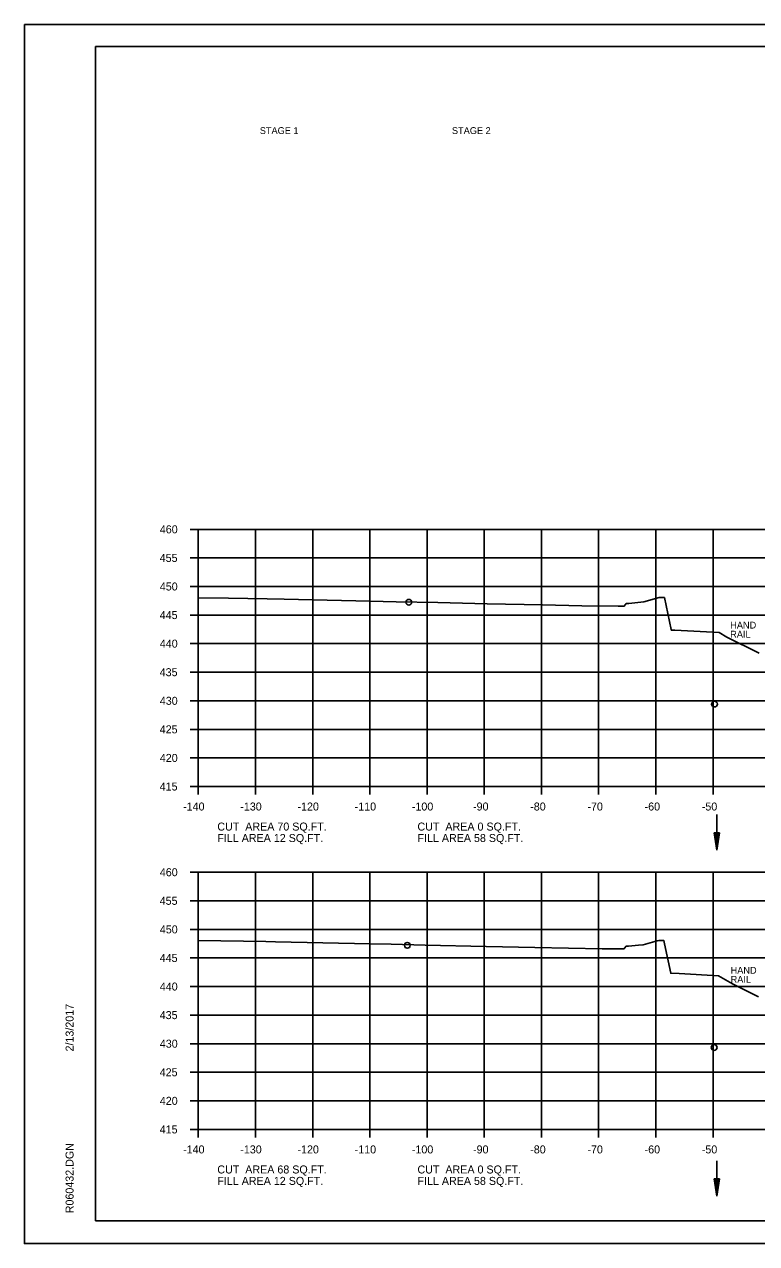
# Model space of a CAD drawing. Extents: x 1538688 to 1540766, y 656250 to 671912.
# Drawn here: x 1538687.8 to 1538815.8, y 663804.7 to 664018.1 of the extents above; entities that cross this region are included whole.
import ezdxf

# ---------------------------------------------------------------- set-up
doc = ezdxf.new("R2010")
doc.units = 0
for name, color, linetype in [('15', 7, 'Continuous'), ('18', 7, 'Continuous'), ('22', 7, 'Continuous'), ('26', 7, 'Continuous'), ('39', 7, 'Continuous'), ('41', 7, 'Continuous'), ('Borings', 7, 'Continuous'), ('Default', 7, 'Continuous'), ('Horizontal Alignment', 7, 'Continuous'), ('RipRap', 7, 'Continuous')]:
    doc.layers.add(name, color=color, linetype=linetype)

msp = doc.modelspace()

# ---------------------------------------------------------------- linework, layer by layer
at = {"layer": '15'}
for p, q in [((1538808.41, 663876.6), (1538808.86, 663873.6)), ((1538808.41, 663876.6), (1538809.31, 663876.6)), ((1538808.48, 663876.6), (1538808.86, 663874.1)), ((1538808.56, 663876.6), (1538808.86, 663874.62)), ((1538808.63, 663876.6), (1538808.86, 663875.12)), ((1538808.71, 663876.6), (1538808.86, 663875.63)), ((1538808.79, 663876.6), (1538808.86, 663876.13)), ((1538809.31, 663876.6), (1538808.86, 663873.6)), ((1538809, 663876.6), (1538808.86, 663875.63)), ((1538809.16, 663876.6), (1538808.86, 663874.62)), ((1538809.23, 663876.6), (1538808.86, 663874.1)), ((1538809.08, 663876.6), (1538808.86, 663875.12)), ((1538808.93, 663876.6), (1538808.86, 663876.13)), ((1538808.41, 663816.04), (1538808.86, 663813.04)), ((1538808.41, 663816.04), (1538809.31, 663816.04)), ((1538808.48, 663816.04), (1538808.86, 663813.54)), ((1538808.56, 663816.04), (1538808.86, 663814.06)), ((1538808.63, 663816.04), (1538808.86, 663814.56)), ((1538808.71, 663816.04), (1538808.86, 663815.06)), ((1538808.79, 663816.04), (1538808.86, 663815.57)), ((1538809.31, 663816.04), (1538808.86, 663813.04)), ((1538809, 663816.04), (1538808.86, 663815.06)), ((1538809.16, 663816.04), (1538808.86, 663814.06)), ((1538809.23, 663816.04), (1538808.86, 663813.54)), ((1538809.08, 663816.04), (1538808.86, 663814.56)), ((1538808.93, 663816.04), (1538808.86, 663815.57))]:
    msp.add_line(p, q, dxfattribs=at)
at = {"layer": '18'}
for points in [[(1538718.18, 663917.75), (1538723.43, 663917.68), (1538730.23, 663917.55), (1538733.18, 663917.48), (1538748.22, 663917.13), (1538752.76, 663917.04), (1538760.05, 663916.88), (1538768.68, 663916.68), (1538778.39, 663916.48), (1538785.26, 663916.34), (1538791.57, 663916.27), (1538792.66, 663916.29), (1538792.81, 663916.48), (1538793.01, 663916.74), (1538793.2, 663916.74), (1538793.46, 663916.74), (1538796.06, 663917), (1538796.08, 663917.01), (1538796.09, 663917.01), (1538798.77, 663917.77), (1538798.79, 663917.77), (1538799.67, 663917.77), (1538800.87, 663912.16), (1538800.88, 663912.09), (1538801.53, 663912.06), (1538809.25, 663911.65), (1538810.6, 663910.86), (1538816.24, 663908.05)], [(1538718.18, 663857.78), (1538726.08, 663857.67), (1538729.97, 663857.6), (1538731.67, 663857.56), (1538748.26, 663857.17), (1538751.92, 663857.1), (1538757.84, 663856.97), (1538768.49, 663856.73), (1538777.04, 663856.55), (1538788.82, 663856.31), (1538791.25, 663856.28), (1538792.62, 663856.3), (1538792.71, 663856.43), (1538792.97, 663856.75), (1538793.09, 663856.75), (1538793.42, 663856.75), (1538795.15, 663856.93), (1538795.99, 663857.01), (1538798.41, 663857.7), (1538798.68, 663857.76), (1538799.5, 663857.77), (1538799.58, 663857.77), (1538799.69, 663857.21), (1538800.79, 663852.04), (1538802.24, 663851.97), (1538809.13, 663851.61), (1538811.59, 663850.16), (1538816.15, 663847.9)]]:
    msp.add_lwpolyline(points, dxfattribs=at)
at = {"layer": '22'}
for p, q in [((1538718.18, 663929.71), (1538998.18, 663929.71)), ((1538718.18, 663884.71), (1538718.18, 663929.71)), ((1538728.18, 663884.71), (1538728.18, 663929.71)), ((1538738.18, 663884.71), (1538738.18, 663929.71)), ((1538748.18, 663884.71), (1538748.18, 663929.71)), ((1538758.18, 663884.71), (1538758.18, 663929.71)), ((1538768.18, 663884.71), (1538768.18, 663929.71)), ((1538778.18, 663884.71), (1538778.18, 663929.71)), ((1538788.18, 663884.71), (1538788.18, 663929.71)), ((1538798.18, 663884.71), (1538798.18, 663929.71)), ((1538808.18, 663884.71), (1538808.18, 663929.71)), ((1538718.18, 663924.71), (1538998.18, 663924.71)), ((1538718.18, 663919.71), (1538998.18, 663919.71)), ((1538718.18, 663914.71), (1538998.18, 663914.71)), ((1538718.18, 663909.71), (1538998.18, 663909.71)), ((1538718.18, 663904.71), (1538998.18, 663904.71)), ((1538718.18, 663899.71), (1538998.18, 663899.71)), ((1538718.18, 663894.71), (1538998.18, 663894.71)), ((1538718.18, 663889.71), (1538998.18, 663889.71)), ((1538718.18, 663884.71), (1538998.18, 663884.71)), ((1538718.18, 663869.71), (1538998.18, 663869.71)), ((1538718.18, 663824.71), (1538718.18, 663869.71)), ((1538728.18, 663824.71), (1538728.18, 663869.71)), ((1538738.18, 663824.71), (1538738.18, 663869.71)), ((1538748.18, 663824.71), (1538748.18, 663869.71)), ((1538758.18, 663824.71), (1538758.18, 663869.71)), ((1538768.18, 663824.71), (1538768.18, 663869.71)), ((1538778.18, 663824.71), (1538778.18, 663869.71)), ((1538788.18, 663824.71), (1538788.18, 663869.71)), ((1538798.18, 663824.71), (1538798.18, 663869.71)), ((1538808.18, 663824.71), (1538808.18, 663869.71)), ((1538718.18, 663864.71), (1538998.18, 663864.71)), ((1538718.18, 663859.71), (1538998.18, 663859.71)), ((1538718.18, 663854.71), (1538998.18, 663854.71)), ((1538718.18, 663849.71), (1538998.18, 663849.71)), ((1538718.18, 663844.71), (1538998.18, 663844.71)), ((1538718.18, 663839.71), (1538998.18, 663839.71)), ((1538718.18, 663834.71), (1538998.18, 663834.71)), ((1538718.18, 663829.71), (1538998.18, 663829.71)), ((1538718.18, 663824.71), (1538998.18, 663824.71))]:
    msp.add_line(p, q, dxfattribs=at)
at = {"layer": '26'}
for p, q in [((1538687.78, 664018.06), (1539021.11, 664018.06)), ((1538687.78, 663804.73), (1539021.11, 663804.73))]:
    msp.add_line(p, q, dxfattribs=at)
msp.add_lwpolyline([(1538687.77, 664018.06), (1539021.11, 664018.06), (1539021.11, 663804.73), (1538687.77, 663804.73)], close=True, dxfattribs=at)
for centre in [(1538754.99, 663916.95), (1538808.44, 663899.13), (1538754.73, 663856.92), (1538808.38, 663839.04)]:
    msp.add_circle(centre, 0.5, dxfattribs=at)
at = {"layer": '39'}
for p, q in [((1538808.86, 663879.79), (1538808.86, 663873.6)), ((1538808.86, 663819.23), (1538808.86, 663813.04))]:
    msp.add_line(p, q, dxfattribs=at)
at = {"layer": 'Borings'}
for p, q in [((1538716.78, 663929.71), (1538718.18, 663929.71)), ((1538718.18, 663884.71), (1538718.18, 663929.71)), ((1538716.78, 663924.71), (1538718.18, 663924.71)), ((1538716.78, 663919.71), (1538718.18, 663919.71)), ((1538716.78, 663914.71), (1538718.18, 663914.71)), ((1538716.78, 663909.71), (1538718.18, 663909.71)), ((1538716.78, 663904.71), (1538718.18, 663904.71)), ((1538716.78, 663899.71), (1538718.18, 663899.71)), ((1538716.78, 663894.71), (1538718.18, 663894.71)), ((1538716.78, 663889.71), (1538718.18, 663889.71)), ((1538716.78, 663884.71), (1538718.18, 663884.71)), ((1538718.18, 663884.71), (1538998.18, 663884.71)), ((1538718.18, 663883.31), (1538718.18, 663884.71)), ((1538728.18, 663883.31), (1538728.18, 663884.71)), ((1538738.18, 663883.31), (1538738.18, 663884.71)), ((1538748.18, 663883.31), (1538748.18, 663884.71)), ((1538758.18, 663883.31), (1538758.18, 663884.71)), ((1538768.18, 663883.31), (1538768.18, 663884.71)), ((1538778.18, 663883.31), (1538778.18, 663884.71)), ((1538788.18, 663883.31), (1538788.18, 663884.71)), ((1538798.18, 663883.31), (1538798.18, 663884.71)), ((1538808.18, 663883.31), (1538808.18, 663884.71)), ((1538716.78, 663869.71), (1538718.18, 663869.71)), ((1538718.18, 663824.71), (1538718.18, 663869.71)), ((1538716.78, 663864.71), (1538718.18, 663864.71)), ((1538716.78, 663859.71), (1538718.18, 663859.71)), ((1538716.78, 663854.71), (1538718.18, 663854.71)), ((1538716.78, 663849.71), (1538718.18, 663849.71)), ((1538716.78, 663844.71), (1538718.18, 663844.71)), ((1538716.78, 663839.71), (1538718.18, 663839.71)), ((1538716.78, 663834.71), (1538718.18, 663834.71)), ((1538716.78, 663829.71), (1538718.18, 663829.71)), ((1538716.78, 663824.71), (1538718.18, 663824.71)), ((1538718.18, 663824.71), (1538998.18, 663824.71)), ((1538718.18, 663823.31), (1538718.18, 663824.71)), ((1538728.18, 663823.31), (1538728.18, 663824.71)), ((1538738.18, 663823.31), (1538738.18, 663824.71)), ((1538748.18, 663823.31), (1538748.18, 663824.71)), ((1538758.18, 663823.31), (1538758.18, 663824.71)), ((1538768.18, 663823.31), (1538768.18, 663824.71)), ((1538778.18, 663823.31), (1538778.18, 663824.71)), ((1538788.18, 663823.31), (1538788.18, 663824.71)), ((1538798.18, 663823.31), (1538798.18, 663824.71)), ((1538808.18, 663823.31), (1538808.18, 663824.71))]:
    msp.add_line(p, q, dxfattribs=at)
at = {"layer": 'RipRap'}
for p, q in [((1538700.18, 664014.17), (1539016.36, 664014.17)), ((1538700.18, 663808.71), (1538700.18, 664014.17)), ((1538700.18, 663808.71), (1538700.18, 663808.71)), ((1539016.36, 663808.71), (1538700.18, 663808.71))]:
    msp.add_line(p, q, dxfattribs=at)

# ---------------------------------------------------------------- texts
at = {"layer": '41'}
for s, p in [('HAND', (1538811.19, 663912.35)), ('RAIL', (1538811.19, 663910.76)), ('HAND', (1538811.26, 663851.95)), ('RAIL', (1538811.26, 663850.36))]:
    msp.add_text(s, height=1.2, dxfattribs=at).set_placement(p)
at = {"layer": 'Default'}
for s, p in [('STAGE 1', (1538728.93, 663998.88)), ('STAGE 2', (1538762.53, 663998.88))]:
    msp.add_text(s, height=1.2, dxfattribs=at).set_placement(p)
at = {"layer": 'Horizontal Alignment'}
for s, p in [('460', (1538711.45, 663929.01)), ('455', (1538711.43, 663924.01)), ('450', (1538711.45, 663919.01)), ('445', (1538711.43, 663914.01)), ('440', (1538711.45, 663909.01)), ('435', (1538711.43, 663904.01)), ('430', (1538711.45, 663899.01)), ('425', (1538711.43, 663894.01)), ('420', (1538711.45, 663889.01)), ('415', (1538711.43, 663884.01)), ('-140', (1538715.52, 663880.51)), ('-130', (1538725.52, 663880.51)), ('-120', (1538735.52, 663880.51)), ('-110', (1538745.52, 663880.51)), ('-100', (1538755.52, 663880.51)), ('-90', (1538766.22, 663880.51)), ('-80', (1538776.22, 663880.51)), ('-70', (1538786.22, 663880.51)), ('-60', (1538796.22, 663880.51)), ('-50', (1538806.22, 663880.51)), ('CUT  AREA 70 SQ.FT.', (1538721.5, 663877)), ('CUT  AREA 0 SQ.FT.', (1538756.5, 663877)), ('FILL AREA 12 SQ.FT.', (1538721.5, 663875)), ('FILL AREA 58 SQ.FT.', (1538756.5, 663875)), ('460', (1538711.45, 663869.01)), ('455', (1538711.43, 663864.01)), ('450', (1538711.45, 663859.01)), ('445', (1538711.43, 663854.01)), ('440', (1538711.45, 663849.01)), ('435', (1538711.43, 663844.01)), ('430', (1538711.45, 663839.01)), ('425', (1538711.43, 663834.01)), ('420', (1538711.45, 663829.01)), ('415', (1538711.43, 663824.01)), ('-140', (1538715.52, 663820.51)), ('-130', (1538725.52, 663820.51)), ('-120', (1538735.52, 663820.51)), ('-110', (1538745.52, 663820.51)), ('-100', (1538755.52, 663820.51)), ('-90', (1538766.22, 663820.51)), ('-80', (1538776.22, 663820.51)), ('-70', (1538786.22, 663820.51)), ('-60', (1538796.22, 663820.51)), ('-50', (1538806.22, 663820.51)), ('CUT  AREA 68 SQ.FT.', (1538721.5, 663817)), ('CUT  AREA 0 SQ.FT.', (1538756.5, 663817)), ('FILL AREA 12 SQ.FT.', (1538721.5, 663815)), ('FILL AREA 58 SQ.FT.', (1538756.5, 663815))]:
    msp.add_text(s, height=1.4, dxfattribs=at).set_placement(p)
at = {"layer": 'RipRap'}
for s, p in [('2/13/2017', (1538696.37, 663838.35)), ('R060432.DGN', (1538696.37, 663810.04))]:
    msp.add_text(s, height=1.4, rotation=90, dxfattribs=at).set_placement(p)

doc.saveas('drawing.dxf')
